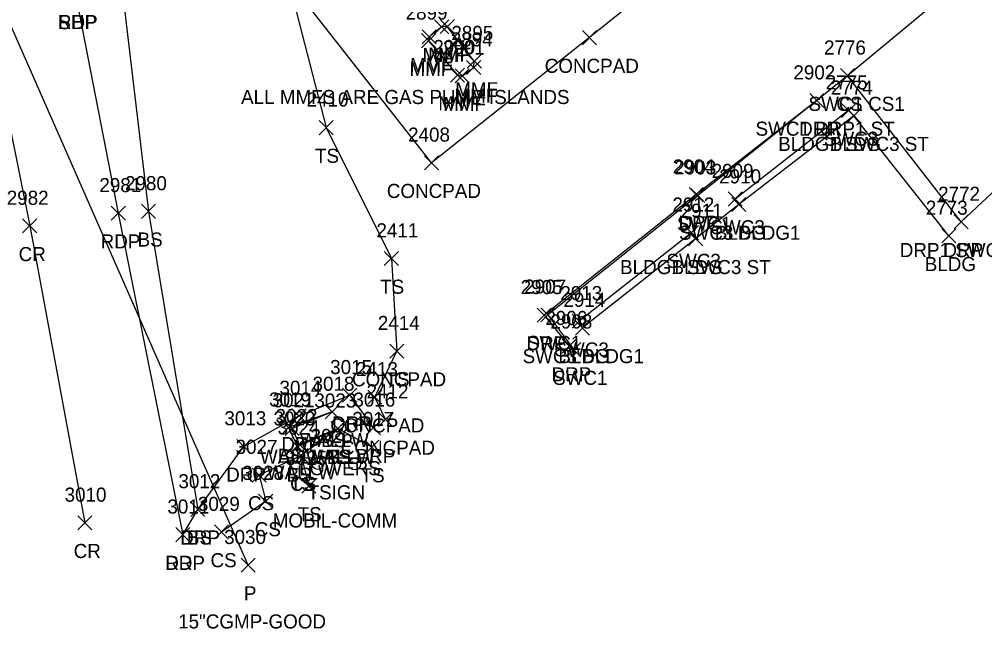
# Model space of a CAD drawing. Extents: x 1504228 to 1506103, y 437717 to 440106.
# Drawn here: x 1505272.1 to 1505409.2, y 437898.2 to 437984.7 of the extents above; entities that cross this region are included whole.
import ezdxf

# ---------------------------------------------------------------- set-up
doc = ezdxf.new("R2010")
doc.units = 0
for name, color, linetype in [('D_A', 7, 'Continuous'), ('D_C', 7, 'Continuous'), ('D_I', 7, 'Continuous'), ('D_TIC', 7, 'Continuous'), ('DCP', 7, 'Continuous'), ('L_A', 7, 'Continuous'), ('L_C', 7, 'Continuous'), ('L_I', 7, 'Continuous'), ('L_TIC', 7, 'Continuous'), ('LBC', 7, 'Continuous'), ('LDEFAULT', 7, 'Continuous'), ('LELB', 7, 'Continuous'), ('LS', 7, 'Continuous'), ('LW', 7, 'Continuous'), ('P_A', 7, 'Continuous'), ('P_I', 7, 'Continuous'), ('P_TIC', 7, 'Continuous'), ('PET', 7, 'Continuous'), ('PRC', 7, 'Continuous'), ('R_A', 7, 'Continuous'), ('R_I', 7, 'Continuous'), ('R_TIC', 7, 'Continuous'), ('RDP', 7, 'Continuous'), ('RSW', 7, 'Continuous'), ('S_A', 7, 'Continuous'), ('S_C', 7, 'Continuous'), ('S_I', 7, 'Continuous'), ('SSGN', 7, 'Continuous')]:
    doc.layers.add(name, color=color, linetype=linetype)

msp = doc.modelspace()

# ---------------------------------------------------------------- linework, layer by layer
at = {"layer": 'D_TIC'}
for points in [[(1505303.61, 437906.19), (1505305.61, 437908.19)], [(1505305.61, 437906.19), (1505303.61, 437908.19)]]:
    msp.add_lwpolyline(points, dxfattribs=at)
at = {"layer": 'DCP'}
msp.add_lwpolyline([(1505304.61, 437907.19), (1505247.15, 438037.69)], dxfattribs=at)
at = {"layer": 'L_TIC'}
for points in [[(1505331.09, 437982.62), (1505333.09, 437984.62)], [(1505333.09, 437982.62), (1505331.09, 437984.62)], [(1505331.89, 437982.68), (1505333.89, 437984.68)], [(1505333.89, 437982.68), (1505331.89, 437984.68)], [(1505329.3, 437981.23), (1505331.3, 437983.23)], [(1505331.3, 437981.23), (1505329.3, 437983.23)], [(1505352.08, 437981.1), (1505354.08, 437983.1)], [(1505354.08, 437981.1), (1505352.08, 437983.1)], [(1505329.24, 437980.67), (1505331.24, 437982.67)], [(1505331.24, 437980.67), (1505329.24, 437982.67)], [(1505335.64, 437976.85), (1505337.64, 437978.85)], [(1505337.64, 437976.85), (1505335.64, 437978.85)], [(1505335.73, 437977.77), (1505337.73, 437979.77)], [(1505337.73, 437977.77), (1505335.73, 437979.77)], [(1505333.33, 437975.77), (1505335.33, 437977.77)], [(1505335.33, 437975.77), (1505333.33, 437977.77)], [(1505334.01, 437975.68), (1505336.01, 437977.68)], [(1505336.01, 437975.68), (1505334.01, 437977.68)], [(1505388.73, 437975.7), (1505390.73, 437977.7)], [(1505390.73, 437975.7), (1505388.73, 437977.7)], [(1505389.64, 437970.01), (1505391.64, 437972.01)], [(1505391.64, 437970.01), (1505389.64, 437972.01)], [(1505314.68, 437968.32), (1505316.68, 437970.32)], [(1505316.68, 437968.32), (1505314.68, 437970.32)], [(1505329.65, 437963.33), (1505331.65, 437965.33)], [(1505331.65, 437963.33), (1505329.65, 437965.33)], [(1505289.45, 437956.43), (1505291.45, 437958.43)], [(1505291.45, 437956.43), (1505289.45, 437958.43)], [(1505373.3, 437957.4), (1505375.3, 437959.4)], [(1505375.3, 437957.4), (1505373.3, 437959.4)], [(1505367.17, 437952.52), (1505369.17, 437954.52)], [(1505369.17, 437952.52), (1505367.17, 437954.52)], [(1505403.13, 437952.95), (1505405.13, 437954.95)], [(1505405.13, 437952.95), (1505403.13, 437954.95)], [(1505323.94, 437949.73), (1505325.94, 437951.73)], [(1505325.94, 437949.73), (1505323.94, 437951.73)], [(1505351.08, 437939.87), (1505353.08, 437941.87)], [(1505353.08, 437939.87), (1505351.08, 437941.87)], [(1505324.71, 437936.58), (1505326.71, 437938.58)], [(1505326.71, 437936.58), (1505324.71, 437938.58)], [(1505324.71, 437936.58), (1505326.71, 437938.58)], [(1505326.71, 437936.58), (1505324.71, 437938.58)], [(1505321.61, 437930.03), (1505323.61, 437932.03)], [(1505323.61, 437930.03), (1505321.61, 437932.03)], [(1505315.52, 437927.95), (1505317.52, 437929.95)], [(1505317.52, 437927.95), (1505315.52, 437929.95)], [(1505315.52, 437927.95), (1505317.52, 437929.95)], [(1505317.52, 437927.95), (1505315.52, 437929.95)], [(1505323.12, 437926.87), (1505325.12, 437928.87)], [(1505325.12, 437926.87), (1505323.12, 437928.87)], [(1505309.35, 437925.72), (1505311.35, 437927.72)], [(1505311.35, 437925.72), (1505309.35, 437927.72)], [(1505309.86, 437925.6), (1505311.86, 437927.6)], [(1505311.86, 437925.6), (1505309.86, 437927.6)], [(1505316.34, 437925.57), (1505318.34, 437927.57)], [(1505318.34, 437925.57), (1505316.34, 437927.57)], [(1505316.34, 437925.57), (1505318.34, 437927.57)], [(1505318.34, 437925.57), (1505316.34, 437927.57)], [(1505316.34, 437925.57), (1505318.34, 437927.57)], [(1505318.34, 437925.57), (1505316.34, 437927.57)], [(1505310.83, 437923.36), (1505312.83, 437925.36)], [(1505312.83, 437923.36), (1505310.83, 437925.36)], [(1505310.62, 437923.02), (1505312.62, 437925.02)], [(1505312.62, 437923.02), (1505310.62, 437925.02)], [(1505321.17, 437922.95), (1505323.17, 437924.95)], [(1505323.17, 437922.95), (1505321.17, 437924.95)], [(1505311.12, 437921.74), (1505313.12, 437923.74)], [(1505313.12, 437921.74), (1505311.12, 437923.74)], [(1505311.12, 437921.74), (1505313.12, 437923.74)], [(1505313.12, 437921.74), (1505311.12, 437923.74)], [(1505305.15, 437918.98), (1505307.15, 437920.98)], [(1505307.15, 437918.98), (1505305.15, 437920.98)], [(1505312.22, 437917.42), (1505314.22, 437919.42)], [(1505314.22, 437917.42), (1505312.22, 437919.42)], [(1505306.09, 437915.29), (1505308.09, 437917.29)], [(1505308.09, 437915.29), (1505306.09, 437917.29)], [(1505296.46, 437914.11), (1505298.46, 437916.11)], [(1505298.46, 437914.11), (1505296.46, 437916.11)], [(1505299.81, 437910.89), (1505301.81, 437912.89)], [(1505301.81, 437910.89), (1505299.81, 437912.89)]]:
    msp.add_lwpolyline(points, dxfattribs=at)
at = {"layer": 'LBC'}
msp.add_lwpolyline([(1505404.13, 437953.95), (1505390.64, 437971.01), (1505374.3, 437958.4), (1505368.17, 437953.52), (1505352.08, 437940.87)], dxfattribs=at)
at = {"layer": 'LDEFAULT'}
for points in [[(1505336.64, 437977.85), (1505336.73, 437978.77), (1505332.89, 437983.68), (1505332.09, 437983.62), (1505330.3, 437982.23), (1505330.24, 437981.67), (1505334.33, 437976.77), (1505335.01, 437976.68)], [(1505335.01, 437976.68), (1505336.64, 437977.85)]]:
    msp.add_lwpolyline(points, dxfattribs=at)
at = {"layer": 'LELB'}
for points in [[(1505421.13, 438005.11), (1505393.63, 438017.06), (1505362.36, 438036.73), (1505342.78, 438047.85), (1505307.15, 438055.11), (1505288.67, 438055.35), (1505284.05, 438043.11), (1505284.37, 438029.86), (1505284.78, 438012.71), (1505286.62, 437989.76), (1505290.45, 437957.43), (1505297.46, 437915.11)], [(1505419.22, 438002.12), (1505405.77, 437989.96), (1505389.73, 437976.7)], [(1505310.28, 437990.32), (1505315.68, 437969.32), (1505324.94, 437950.73), (1505325.71, 437937.58)], [(1505316.52, 437928.95), (1505310.35, 437926.72), (1505311.62, 437924.02), (1505317.34, 437926.57)], [(1505322.17, 437923.95), (1505317.34, 437926.57), (1505312.12, 437922.74), (1505313.22, 437918.42)], [(1505312.12, 437922.74), (1505306.15, 437919.98), (1505307.09, 437916.29), (1505300.81, 437911.89)]]:
    msp.add_lwpolyline(points, dxfattribs=at)
at = {"layer": 'LS'}
for points in [[(1505346.53, 438028.16), (1505371.38, 437996.81), (1505353.08, 437982.1), (1505330.65, 437964.33), (1505310.28, 437990.32)], [(1505324.12, 437927.87), (1505322.61, 437931.03), (1505325.71, 437937.58)]]:
    msp.add_lwpolyline(points, dxfattribs=at)
at = {"layer": 'LW'}
msp.add_lwpolyline([(1505316.52, 437928.95), (1505310.86, 437926.6), (1505311.83, 437924.36), (1505317.34, 437926.57)], dxfattribs=at)
at = {"layer": 'P_TIC'}
for points in [[(1505285.15, 437956.16), (1505287.15, 437958.16)], [(1505287.15, 437956.16), (1505285.15, 437958.16)], [(1505272.56, 437954.36), (1505274.56, 437956.36)], [(1505274.56, 437954.36), (1505272.56, 437956.36)], [(1505280.38, 437912.2), (1505282.38, 437914.2)], [(1505282.38, 437912.2), (1505280.38, 437914.2)], [(1505294.33, 437910.51), (1505296.33, 437912.51)], [(1505296.33, 437910.51), (1505294.33, 437912.51)]]:
    msp.add_lwpolyline(points, dxfattribs=at)
at = {"layer": 'PET'}
msp.add_lwpolyline([(1505397.24, 438032.03), (1505368.76, 438049.08), (1505341.98, 438064), (1505317.03, 438071.38), (1505301.97, 438067.95), (1505290.32, 438060.04), (1505279.39, 438043.77), (1505275.68, 438025.7), (1505280.08, 437988.31), (1505286.15, 437957.16), (1505295.33, 437911.51)], dxfattribs=at)
at = {"layer": 'PRC'}
msp.add_lwpolyline([(1505229.48, 438143.45), (1505234.69, 438118.1), (1505243.62, 438084.86), (1505253.15, 438053.47), (1505260.45, 438023.85), (1505266.19, 437991.87), (1505273.56, 437955.36), (1505281.38, 437913.2)], dxfattribs=at)
at = {"layer": 'R_TIC'}
for points in [[(1505388.73, 437975.7), (1505390.73, 437977.7)], [(1505390.73, 437975.7), (1505388.73, 437977.7)], [(1505384.39, 437972.17), (1505386.39, 437974.17)], [(1505386.39, 437972.17), (1505384.39, 437974.17)], [(1505384.39, 437972.17), (1505386.39, 437974.17)], [(1505386.39, 437972.17), (1505384.39, 437974.17)], [(1505388.91, 437970.75), (1505390.91, 437972.75)], [(1505390.91, 437970.75), (1505388.91, 437972.75)], [(1505389.64, 437970.01), (1505391.64, 437972.01)], [(1505391.64, 437970.01), (1505389.64, 437972.01)], [(1505367.26, 437958.81), (1505369.26, 437960.81)], [(1505369.26, 437958.81), (1505367.26, 437960.81)], [(1505367.48, 437958.67), (1505369.48, 437960.67)], [(1505369.48, 437958.67), (1505367.48, 437960.67)], [(1505372.8, 437958.18), (1505374.8, 437960.18)], [(1505374.8, 437958.18), (1505372.8, 437960.18)], [(1505373.3, 437957.4), (1505375.3, 437959.4)], [(1505375.3, 437957.4), (1505373.3, 437959.4)], [(1505404.88, 437954.93), (1505406.88, 437956.93)], [(1505406.88, 437954.93), (1505404.88, 437956.93)], [(1505404.88, 437954.93), (1505406.88, 437956.93)], [(1505406.88, 437954.93), (1505404.88, 437956.93)], [(1505366.56, 437953.4), (1505368.56, 437955.4)], [(1505368.56, 437953.4), (1505366.56, 437955.4)], [(1505367.17, 437952.52), (1505369.17, 437954.52)], [(1505369.17, 437952.52), (1505367.17, 437954.52)], [(1505345.65, 437941.68), (1505347.65, 437943.68)], [(1505347.65, 437941.68), (1505345.65, 437943.68)], [(1505346.16, 437941.75), (1505348.16, 437943.75)], [(1505348.16, 437941.75), (1505346.16, 437943.75)], [(1505350.64, 437940.82), (1505352.64, 437942.82)], [(1505352.64, 437940.82), (1505350.64, 437942.82)], [(1505351.08, 437939.87), (1505353.08, 437941.87)], [(1505353.08, 437939.87), (1505351.08, 437941.87)], [(1505349.21, 437937.29), (1505351.21, 437939.29)], [(1505351.21, 437937.29), (1505349.21, 437939.29)], [(1505349.88, 437936.79), (1505351.88, 437938.79)], [(1505351.88, 437936.79), (1505349.88, 437938.79)], [(1505318.02, 437930.32), (1505320.02, 437932.32)], [(1505320.02, 437930.32), (1505318.02, 437932.32)], [(1505310.82, 437927.38), (1505312.82, 437929.38)], [(1505312.82, 437927.38), (1505310.82, 437929.38)], [(1505321.38, 437925.7), (1505323.38, 437927.7)], [(1505323.38, 437925.7), (1505321.38, 437927.7)], [(1505302.99, 437923.05), (1505304.99, 437925.05)], [(1505304.99, 437923.05), (1505302.99, 437925.05)], [(1505296.46, 437914.11), (1505298.46, 437916.11)], [(1505298.46, 437914.11), (1505296.46, 437916.11)], [(1505294.33, 437910.51), (1505296.33, 437912.51)], [(1505296.33, 437910.51), (1505294.33, 437912.51)]]:
    msp.add_lwpolyline(points, dxfattribs=at)
at = {"layer": 'RDP'}
for points in [[(1505438.13, 438010.29), (1505428.55, 438010.9), (1505421.13, 438005.11), (1505419.22, 438002.12), (1505421.58, 437997.81), (1505432.97, 437988.13), (1505435.24, 437983.41), (1505417.5, 437966.8), (1505405.88, 437955.93)], [(1505385.39, 437973.17), (1505368.26, 437959.81), (1505346.65, 437942.68), (1505350.21, 437938.29)], [(1505295.33, 437911.51), (1505297.46, 437915.11), (1505303.99, 437924.05), (1505311.82, 437928.38), (1505319.02, 437931.32), (1505322.38, 437926.7)]]:
    msp.add_lwpolyline(points, dxfattribs=at)
at = {"layer": 'RSW'}
for points in [[(1505405.88, 437955.93), (1505389.73, 437976.7), (1505385.39, 437973.17), (1505368.48, 437959.67), (1505347.16, 437942.75), (1505350.88, 437937.79)], [(1505390.64, 437971.01), (1505389.91, 437971.75), (1505373.8, 437959.18), (1505374.3, 437958.4)], [(1505368.17, 437953.52), (1505367.56, 437954.4), (1505351.64, 437941.82), (1505352.08, 437940.87)]]:
    msp.add_lwpolyline(points, dxfattribs=at)
at = {"layer": 'SSGN'}
for p, q in [((1505312.85, 437922.45), (1505321.44, 437922.45)), ((1505316.87, 437921.54), (1505316.87, 437921.54))]:
    msp.add_line(p, q, dxfattribs=at)
for centre in [(1505314.51, 437921.61), (1505319.72, 437921.54)]:
    msp.add_circle(centre, 0.833, dxfattribs=at)

# ---------------------------------------------------------------- texts
at = {"layer": 'D_A'}
msp.add_text('P', height=2, dxfattribs=at).set_placement((1505303.99, 437902.19))
at = {"layer": 'D_C'}
msp.add_text('15"CGMP-GOOD', height=2, dxfattribs=at).set_placement((1505294.65, 437898.19))
at = {"layer": 'D_I'}
msp.add_text('3030', height=2, dxfattribs=at).set_placement((1505301.18, 437910.19))
at = {"layer": 'L_A'}
for s, p in [('MMF', (1505329.37, 437978.62)), ('MMF', (1505330.18, 437978.68)), ('MMF', (1505327.59, 437977.23)), ('CONCPAD', (1505346.73, 437977.1)), ('MMF', (1505327.52, 437976.67)), ('MMF', (1505333.92, 437972.85)), ('MMF', (1505334.01, 437973.77)), ('MMF', (1505331.61, 437971.77)), ('MMF', (1505332.3, 437971.68)), ('CS', (1505388.17, 437971.7)), ('BLDG', (1505387.23, 437966.01)), ('TS', (1505314.09, 437964.32)), ('CONCPAD', (1505324.3, 437959.33)), ('BLDG', (1505370.89, 437953.4)), ('BS', (1505288.89, 437952.43)), ('BLDG', (1505364.76, 437948.52)), ('BLDG', (1505400.72, 437948.95)), ('TS', (1505323.35, 437945.73)), ('BLDG', (1505348.67, 437935.87)), ('CONCPAD', (1505319.35, 437932.58)), ('TS', (1505324.12, 437932.58)), ('CONCPAD', (1505316.26, 437926.03)), ('WALLW', (1505311.94, 437923.95)), ('BS', (1505314.96, 437923.95)), ('CONCPAD', (1505317.76, 437922.87)), ('WALLW', (1505306.27, 437921.6)), ('BS', (1505308.8, 437921.72)), ('WALLW', (1505312.76, 437921.57)), ('TS', (1505315.75, 437921.57)), ('BS', (1505315.78, 437921.57)), ('WALLW', (1505307.24, 437919.36)), ('BS', (1505310.06, 437919.02)), ('TS', (1505310.53, 437917.74)), ('CS', (1505310.56, 437917.74)), ('TS', (1505320.58, 437918.95)), ('CS', (1505304.59, 437914.98)), ('TS', (1505311.63, 437913.42)), ('CS', (1505305.53, 437911.29)), ('BS', (1505295.9, 437910.11)), ('CS', (1505299.25, 437906.89))]:
    msp.add_text(s, height=2, dxfattribs=at).set_placement(p)
at = {"layer": 'L_C'}
for s, p in [('ALL MMFS ARE GAS PUMP ISLANDS', (1505303.59, 437972.67)), ('FLOWERS', (1505310.22, 437919.95))]:
    msp.add_text(s, height=2, dxfattribs=at).set_placement(p)
at = {"layer": 'L_I'}
for s, p in [('2899', (1505326.97, 437984.67)), ('2894', (1505333.38, 437980.85)), ('2895', (1505333.47, 437981.77)), ('2900', (1505330.9, 437979.77)), ('2901', (1505332.24, 437979.68)), ('2776', (1505386.41, 437979.7)), ('2774', (1505387.38, 437974.01)), ('2410', (1505312.9, 437972.32)), ('2408', (1505327.32, 437967.33)), ('2980', (1505287.1, 437960.43)), ('2910', (1505371.52, 437961.4)), ('2911', (1505366.05, 437956.52)), ('2773', (1505400.87, 437956.95)), ('2411', (1505322.82, 437953.73)), ('2914', (1505349.39, 437943.87)), ('2414', (1505323.02, 437940.58)), ('2414', (1505323.02, 437940.58)), ('2413', (1505319.92, 437934.03)), ('3018', (1505313.75, 437931.95)), ('3018', (1505313.75, 437931.95)), ('2412', (1505321.42, 437930.87)), ('3019', (1505307.58, 437929.72)), ('3021', (1505308.08, 437929.6)), ('3023', (1505314, 437929.57)), ('3023', (1505314, 437929.57)), ('3023', (1505314, 437929.57)), ('3022', (1505308.49, 437927.36)), ('3020', (1505308.2, 437927.02)), ('3017', (1505319.4, 437926.95)), ('3024', (1505308.78, 437925.74)), ('3024', (1505308.78, 437925.74)), ('3027', (1505302.81, 437922.98)), ('3025', (1505309.88, 437921.42)), ('3028', (1505303.75, 437919.29)), ('3012', (1505294.69, 437918.11)), ('3029', (1505297.46, 437914.89))]:
    msp.add_text(s, height=2, dxfattribs=at).set_placement(p)
at = {"layer": 'P_A'}
for s, p in [('SHP', (1505277.62, 437983.31)), ('RDP', (1505277.57, 437983.31)), ('RDP', (1505283.64, 437952.16)), ('CR', (1505271.99, 437950.36)), ('CR', (1505279.81, 437908.2)), ('RDP', (1505292.82, 437906.51))]:
    msp.add_text(s, height=2, dxfattribs=at).set_placement(p)
at = {"layer": 'P_I'}
for s, p in [('2981', (1505283.46, 437960.16)), ('2982', (1505270.3, 437958.36)), ('3010', (1505278.52, 437916.2)), ('3011', (1505293.12, 437914.51))]:
    msp.add_text(s, height=2, dxfattribs=at).set_placement(p)
at = {"layer": 'R_A'}
for s, p in [('SWC1 CS1', (1505384.21, 437971.7)), ('SWC1 DRP1 ST', (1505376.68, 437968.17)), ('DRP', (1505382.88, 437968.17)), ('BLDG1 SWC3 ST', (1505379.9, 437966.01)), ('SWC3', (1505386.38, 437966.75)), ('DRP', (1505365.75, 437954.81)), ('SWC1', (1505365.52, 437954.67)), ('SWC3 BLDG1', (1505365.81, 437953.4)), ('SWC3', (1505370.27, 437954.18)), ('DRP1 SWC1 ST', (1505397.17, 437950.93)), ('DRP', (1505403.37, 437950.93)), ('SWC3', (1505364.03, 437949.4)), ('BLDG1 SWC3 ST', (1505357.43, 437948.52)), ('SWC1', (1505344.2, 437937.75)), ('DRP', (1505344.14, 437937.68)), ('SWC3 BLDG1', (1505343.59, 437935.87)), ('SWC3', (1505348.11, 437936.82)), ('DRP', (1505347.7, 437933.29)), ('SWC1', (1505347.92, 437932.79)), ('DRP', (1505316.51, 437926.32)), ('DRP', (1505309.31, 437923.38)), ('DRP', (1505319.87, 437921.7)), ('DRP', (1505301.48, 437919.05)), ('DRP', (1505294.95, 437910.11)), ('DRP', (1505292.82, 437906.51))]:
    msp.add_text(s, height=2, dxfattribs=at).set_placement(p)
at = {"layer": 'R_I'}
for s, p in [('2776', (1505386.41, 437979.7)), ('2902', (1505382.06, 437976.17)), ('2902', (1505382.06, 437976.17)), ('2775', (1505386.65, 437974.75)), ('2774', (1505387.38, 437974.01)), ('2904', (1505364.92, 437962.81)), ('2903', (1505365.14, 437962.67)), ('2909', (1505370.45, 437962.18)), ('2910', (1505371.52, 437961.4)), ('2772', (1505402.62, 437958.93)), ('2772', (1505402.62, 437958.93)), ('2912', (1505364.87, 437957.4)), ('2911', (1505366.05, 437956.52)), ('2905', (1505343.31, 437945.68)), ('2907', (1505343.82, 437945.75)), ('2913', (1505348.95, 437944.82)), ('2914', (1505349.39, 437943.87)), ('2906', (1505346.82, 437941.29)), ('2908', (1505347.54, 437940.79)), ('3015', (1505316.25, 437934.32)), ('3014', (1505309.05, 437931.38)), ('3016', (1505319.55, 437929.7)), ('3013', (1505301.22, 437927.05)), ('3012', (1505294.69, 437918.11)), ('3011', (1505293.12, 437914.51))]:
    msp.add_text(s, height=2, dxfattribs=at).set_placement(p)
at = {"layer": 'S_A'}
msp.add_text('TSIGN', height=2, dxfattribs=at).set_placement((1505313.04, 437916.53))
at = {"layer": 'S_C'}
msp.add_text('MOBIL-COMM', height=2, dxfattribs=at).set_placement((1505308.09, 437912.53))
at = {"layer": 'S_I'}
msp.add_text('3026', height=2, dxfattribs=at).set_placement((1505313.47, 437924.53))

doc.saveas('drawing.dxf')
